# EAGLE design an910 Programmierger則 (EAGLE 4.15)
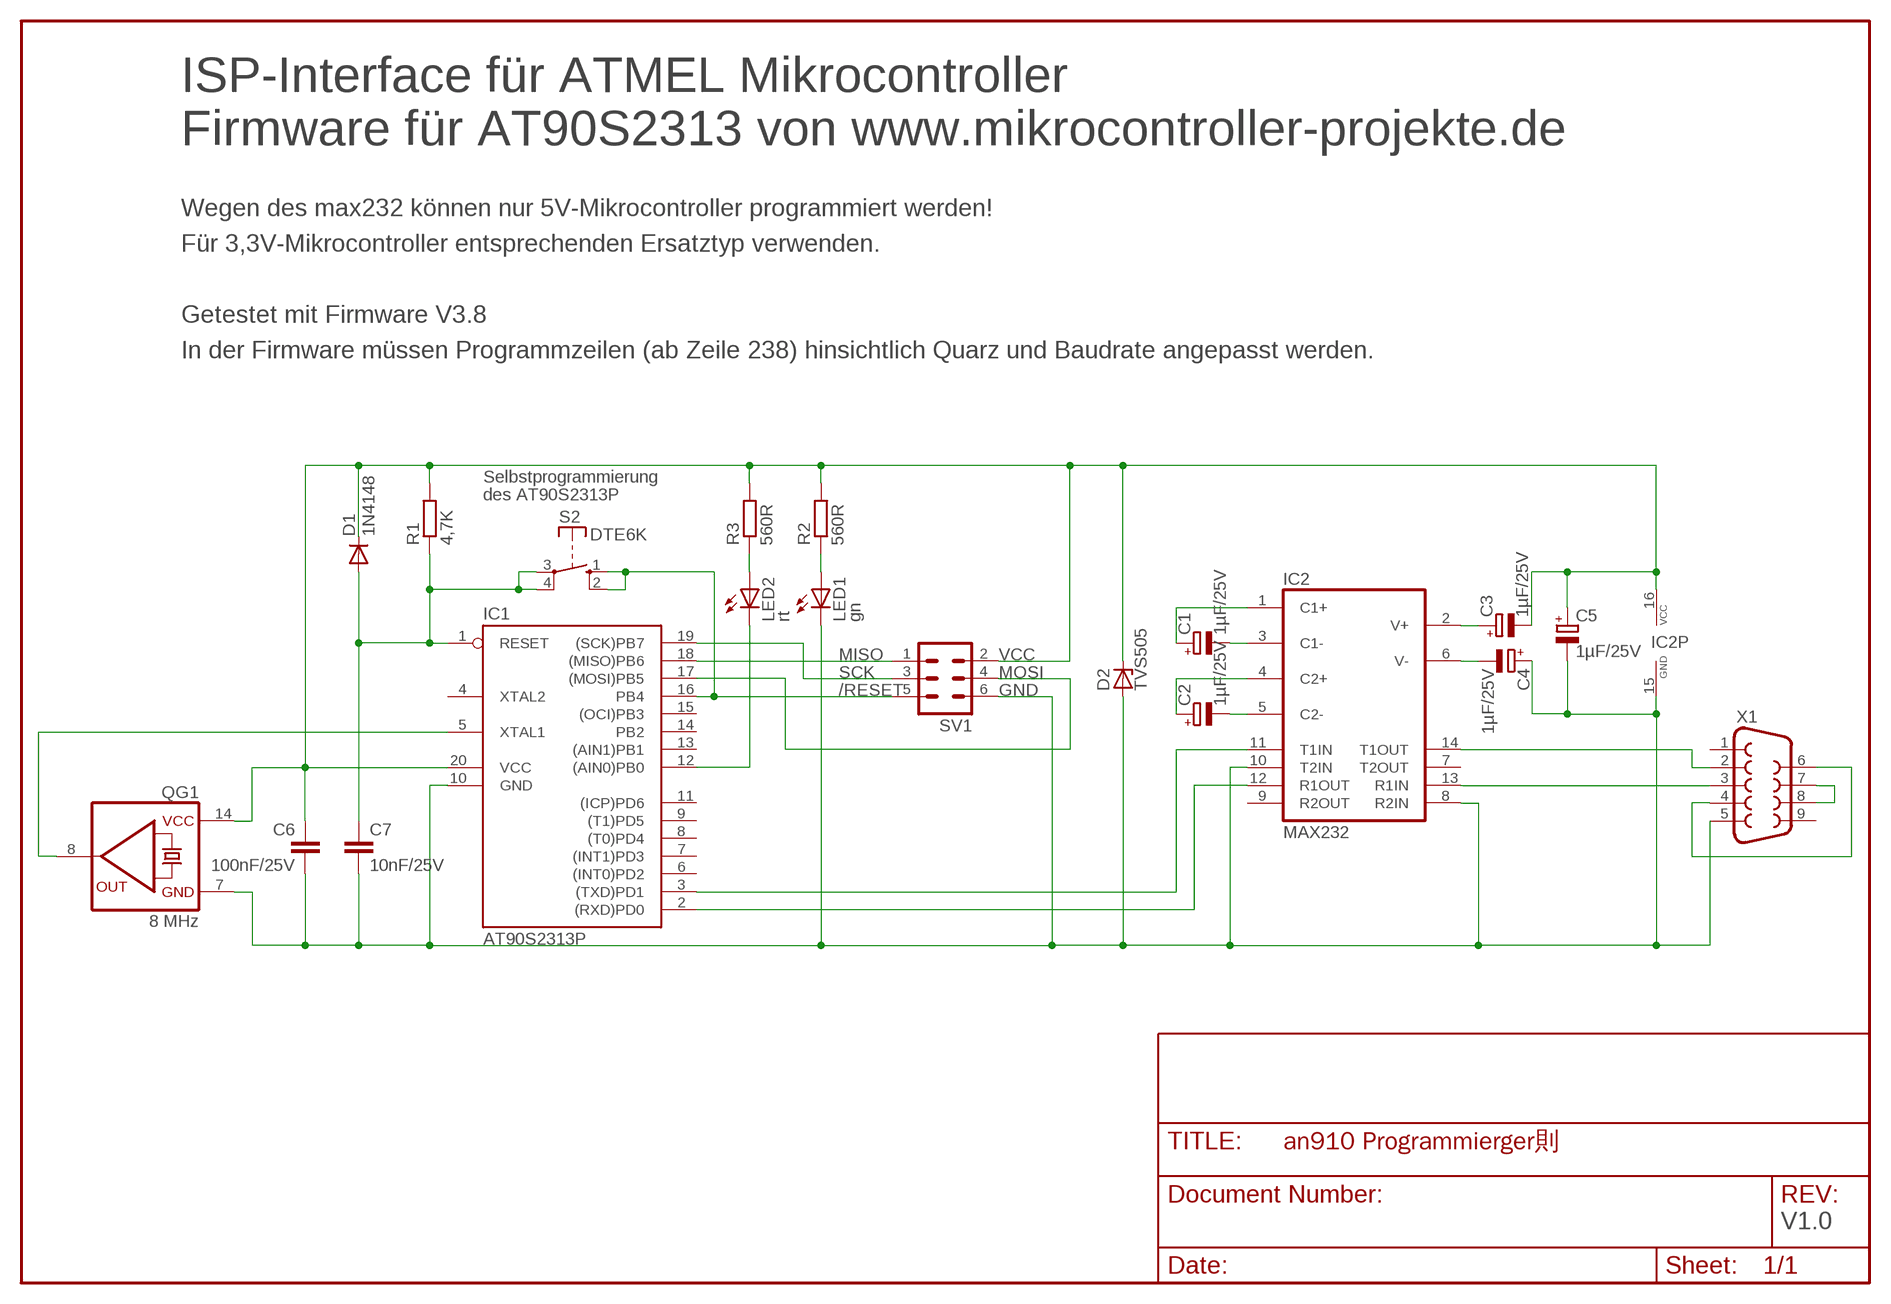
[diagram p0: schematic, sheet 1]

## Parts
C1  1µF/25V  CPOL-EUETR1  [ETR1]
C2  1µF/25V  CPOL-EUETR1  [ETR1]
C3  1µF/25V  CPOL-EUETR1  [ETR1]
C4  1µF/25V  CPOL-EUETR1  [ETR1]
C5  1µF/25V  CPOL-EUETR1  [ETR1]
C6  100nF/25V  C-EU050-030X075  [C050-030X075]
C7  10nF/25V  C-EU050-030X075  [C050-030X075]
D1  1N4148  [DO35-10]
D2  TVS505  ZY  [P1Z12]
IC1  AT90S2313P  [DIL20]
IC2  MAX232  [DIL16]
LED1  gn  LED3MM  [LED3MM]
LED2  rt  LED3MM  [LED3MM]
QG1  8 MHz  QG5860  [DIL14S]
R1  4,7K  R-EU_0207/10  [0207/10]
R2  560R  R-EU_0207/10  [0207/10]
R3  560R  R-EU_0207/10  [0207/10]
S2  DTE6K  [DTE6K]
SV1  MA03-2  [MA03-2]
X1  F09H  [F09H]

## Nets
N$1: C2.- IC2.5(C2-)
N$2: C2.+ IC2.4(C2+)
N$3: C1.- IC2.3(C1-)
N$4: C1.+ IC2.1(C1+)
N$5: IC1.12((AIN0)PB0) LED2.K(C)
N$6: IC1.3((TXD)PD1) IC2.11(T1IN)
N$7: C4.- IC2.6(V-)
N$8: C3.+ IC2.2(V+)
N$9: IC1.18((MISO)PB6) SV1.1
N$10: C3.- C5.+ C6.1 D1.C D2.C IC1.20(VCC) IC2.16(VCC) QG1.14(VCC) R1.2 R2.2 R3.2 SV1.2
N$12: IC1.2((RXD)PD0) IC2.12(R1OUT)
N$13: IC2.14(T1OUT) X1.2
N$14: IC2.13(R1IN) X1.3
N$15: X1.7 X1.8
N$16: X1.4 X1.6
N$17: IC1.19((SCK)PB7) SV1.3
N$18: IC1.5(XTAL1) QG1.8(OUT)
N$19: IC1.17((MOSI)PB5) SV1.4
N$20: IC1.16(PB4) S2.1(S) S2.2(S) SV1.5
N$21: LED1.A R2.1
N$22: C7.1 D1.A IC1.1(RESET) R1.1 S2.3(P) S2.4(P)
N$23: LED2.A R3.1
N$24: C4.+ C5.- C6.2 C7.2 D2.A IC1.10(GND) IC2.8(R2IN) IC2.10(T2IN) IC2.15(GND) LED1.K(C) QG1.7(GND) SV1.6 X1.5
Unconnected: IC1.4(XTAL2) IC1.6((INT0)PD2) IC1.7((INT1)PD3) IC1.8((T0)PD4) IC1.9((T1)PD5) IC1.11((ICP)PD6) IC1.13((AIN1)PB1) IC1.14(PB2) IC1.15((OCI)PB3) IC2.7(T2OUT) IC2.9(R2OUT) X1.1 X1.9

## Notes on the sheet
- ISP-Interface für ATMEL Mikrocontroller
- Firmware für AT90S2313 von www.mikrocontroller-projekte.de
- Wegen des max232 können nur 5V-Mikrocontroller programmiert werden!
- Für 3,3V-Mikrocontroller entsprechenden Ersatztyp verwenden.
- Getestet mit Firmware V3.8
- In der Firmware müssen Programmzeilen (ab Zeile 238) hinsichtlich Quarz und Baudrate angepasst werden.
- Selbstprogrammierung
- des AT90S2313P
- MISO | VCC
- SCK | MOSI
- /RESET | GND
- V1.0

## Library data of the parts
C1-C5 = rcl:CPOL-EU: POLARIZED CAPACITOR, European symbol
C6 C7 = rcl:C-EU: CAPACITOR, European symbol
D1 = diode:1N4148: DIODE
D2 = diode:ZY: Z DIODE
IC1 = atmel:AT90S2313: MICROCONTROLLER 2 Kbytes FLASH 128 bytes SRAM 128 bytes EEPROM UART
IC2 = maxim:MAX232: RS232 TRANSEIVER
LED1 LED2 = led:LED: LED
QG1 = crystal:QG5860: CRYSTAL RESONATOR
R1-R3 = rcl:R-EU_: RESISTOR, European symbol
S2 = switch-misc:DT: ITT SWITCH
SV1 = con-lstb:MA03-2: PIN HEADER
X1 = con-subd:F09: SUB-D

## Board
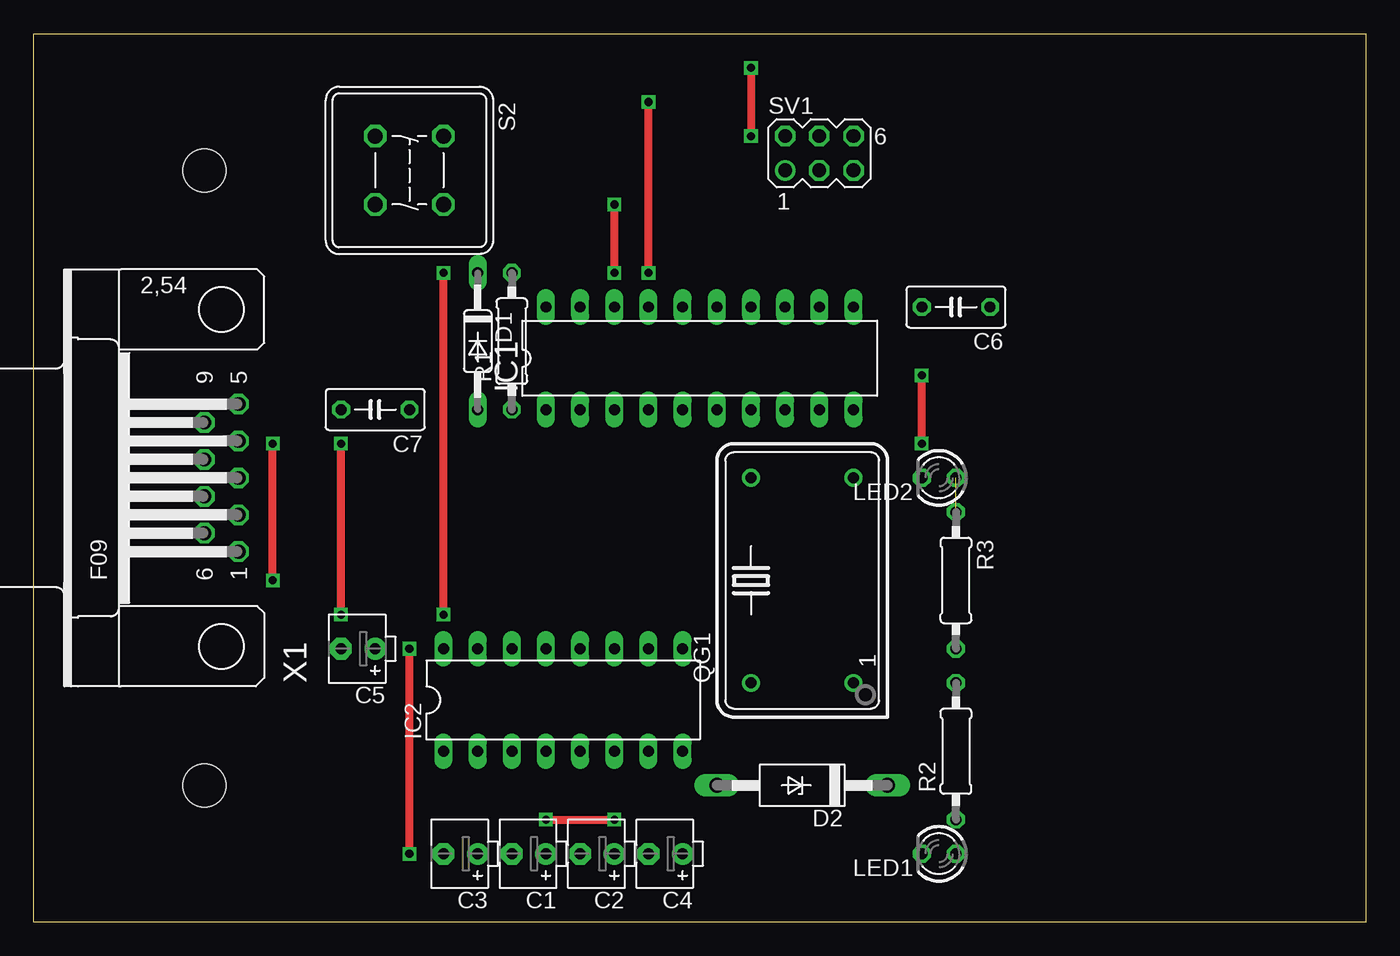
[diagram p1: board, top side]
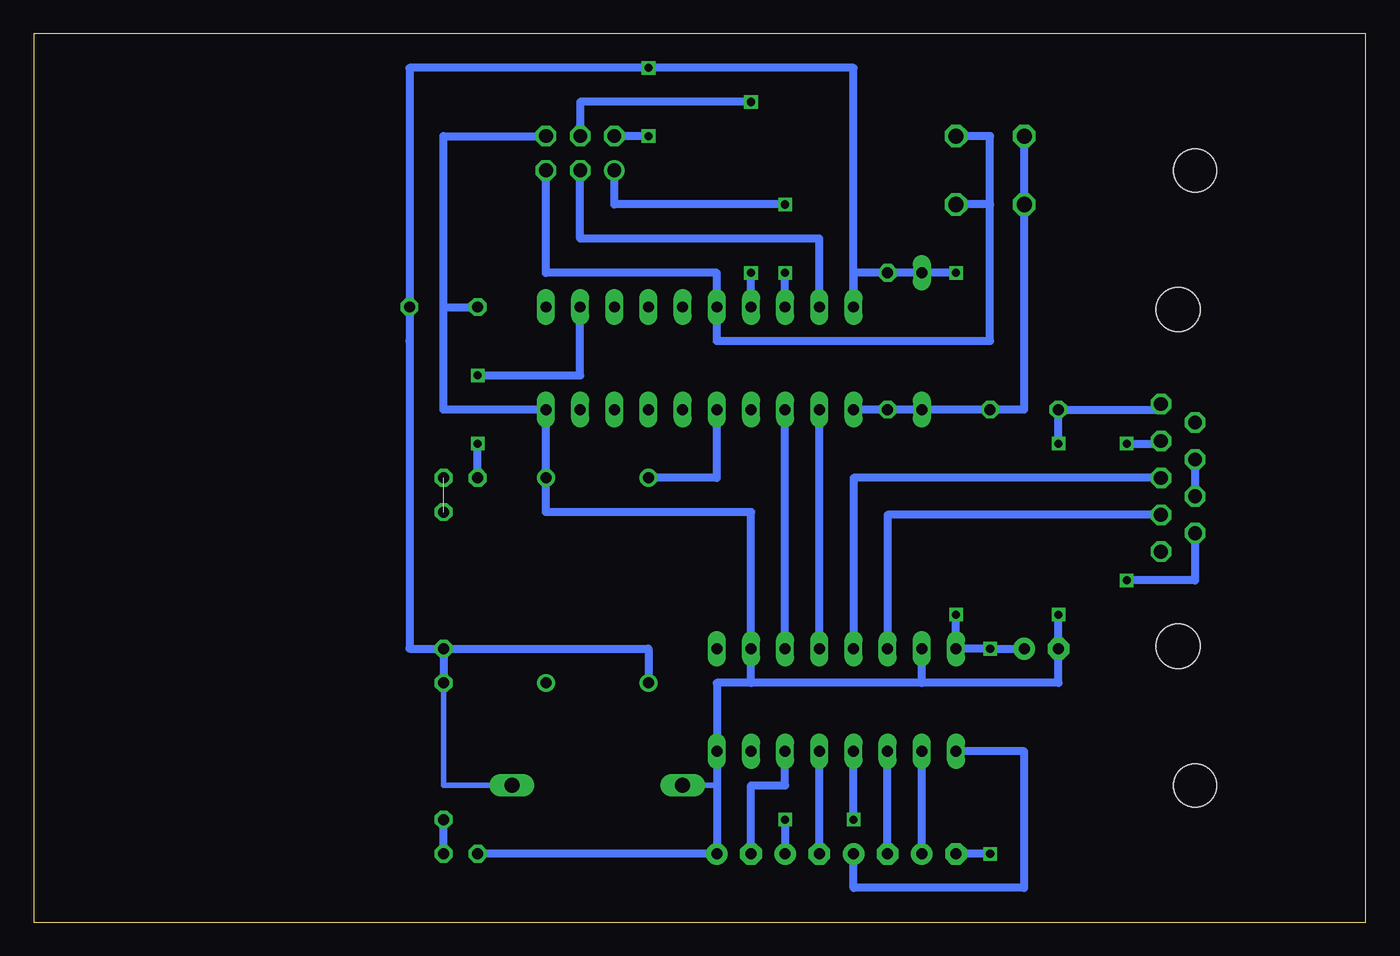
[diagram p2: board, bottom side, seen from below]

Size 99.06 x 66.04 mm. Coordinates in mm from the lower left corner, seen from the top.
Outline: 0,0 0,66.04 99.06,66.04 99.06,0 0,0
Copper layers (1*16): Top 0.035mm / dielectric 1.5mm / Bottom 0.035mm
Design rules "default": minimum track width 10mil, minimum drill 24mil, track to track 8mil, track to pad 8mil, pad to pad 8mil, via to via 8mil, smd to smd 8mil, copper to edge 40mil, drill to drill 8mil, minimum pad ring 10mil, minimum via ring 8mil, stop-mask expansion 4mil, vias tented up to drill 0mil, thermal gap 10mil
Holes 3.2 mm at 12.7,55.88 12.7,10.16

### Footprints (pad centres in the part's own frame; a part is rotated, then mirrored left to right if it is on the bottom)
ETR1 = drill 0.813 pad 1.6 round: + -1.27,0 | drill 0.813 pad 1.6 octagon: - 1.27,0
C050-030X075 = drill 0.813 octagon: 1 -2.54,0; 2 2.54,0
DO35-10 = drill 0.813 long: A 5.08,0; C -5.08,0
P1Z12 = drill 1.118 long: A 6.35,0; C -6.35,0
DIL20 = drill 0.813 long: 1 -11.43,-3.81; 2 -8.89,-3.81; 3 -6.35,-3.81; 4 -3.81,-3.81; 5 -1.27,-3.81; 6 1.27,-3.81; 7 3.81,-3.81; 8 6.35,-3.81; 9 8.89,-3.81; 10 11.43,-3.81; 11 11.43,3.81; 12 8.89,3.81; 13 6.35,3.81; 14 3.81,3.81; 15 1.27,3.81; 16 -1.27,3.81; 17 -3.81,3.81; 18 -6.35,3.81; 19 -8.89,3.81; 20 -11.43,3.81
DIL16 = drill 0.813 long: 1 -8.89,-3.81; 2 -6.35,-3.81; 3 -3.81,-3.81; 4 -1.27,-3.81; 5 1.27,-3.81; 6 3.81,-3.81; 7 6.35,-3.81; 8 8.89,-3.81; 9 8.89,3.81; 10 6.35,3.81; 11 3.81,3.81; 12 1.27,3.81; 13 -1.27,3.81; 14 -3.81,3.81; 15 -6.35,3.81; 16 -8.89,3.81
LED3MM = drill 0.813 octagon: A -1.27,0; K 1.27,0
DIL14S = drill 0.813 round: 1 -7.62,-3.81; 7 7.62,-3.81; 8 7.62,3.81; 14 -7.62,3.81
0207/10 = drill 0.813 octagon: 1 -5.08,0; 2 5.08,0
DTE6K = drill 1.118 octagon: 1 -2.54,2.54; 2 2.54,2.54; 3 2.54,-2.54; 4 -2.54,-2.54
MA03-2 = drill 1.016 round: 1 -2.54,-1.27 | drill 1.016 octagon: 2 -2.54,1.27; 3 0,-1.27; 4 0,1.27; 5 2.54,-1.27; 6 2.54,1.27
F09H = drill 1.016 octagon: 1 -5.486,-1.27; 2 -2.743,-1.27; 3 0,-1.27; 4 2.743,-1.27; 5 5.486,-1.27; 6 -4.115,1.27; 7 -1.372,1.27; 8 1.372,1.27; 9 4.115,1.27 | hole 3.302: -12.522,0; 12.522,0

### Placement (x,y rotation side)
C1  36.83,5.08 180 top
C2  41.91,5.08 180 top
C3  31.75,5.08 180 top
C4  46.99,5.08 180 top
C5  24.13,20.32 180 top
C6  68.58,45.72 180 top
C7  25.4,38.1 180 top
D1  33.02,43.18 270 top
D2  57.15,10.16 180 top
IC1  49.53,41.91 0 top
IC2  39.37,16.51 0 top
LED1  67.31,5.08 180 top
LED2  67.31,33.02 180 top
QG1  57.15,25.4 90 top
R1  35.56,43.18 90 top
R2  68.58,12.7 90 top
R3  68.58,25.4 270 top
S2  27.94,55.88 270 top
SV1  58.42,57.15 0 top
X1  13.97,33.02 90 top

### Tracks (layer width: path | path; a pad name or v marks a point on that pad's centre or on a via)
N$1
  Bottom 0.61: C2.- IC2.5
N$2  (via drill 0.6)
  Top 0.61: v38.1,7.62 v43.18,7.62
  Bottom 0.61: v43.18,7.62 C2.+ | v38.1,7.62 IC2.4
N$3
  Bottom 0.61: C1.- IC2.3
N$4
  Bottom 0.61: C1.+ 38.1,2.54 25.4,2.54 25.4,12.7 IC2.1
N$5  (via drill 0.6)
  Top 0.61: v66.04,35.56 v66.04,40.64
  Bottom 0.61: IC1.12 58.42,40.64 v66.04,40.64 | LED2.K v66.04,35.56
N$6
  Bottom 0.61: IC2.11 IC1.3
N$7
  Bottom 0.61: C4.- 45.72,10.16 43.18,10.16 IC2.6
N$8
  Bottom 0.61: C3.+ IC2.2
N$9  (via drill 0.6)
  Top 0.61: v43.18,48.26 v43.18,53.34
  Bottom 0.61: v43.18,53.34 55.88,53.34 SV1.1 | IC1.18 v43.18,48.26
N$10  (via drill 0.6)
  Top 0.61: v27.94,5.08 v27.94,20.32 | v30.48,22.86 v30.48,48.26 | v53.34,63.5 v53.34,58.42
  Bottom 0.406: D2.C 68.58,10.16 R2.2
  Bottom 0.61: v27.94,5.08 C3.- | v27.94,20.32 IC2.16 | v27.94,20.32 C5.+ | v27.94,20.32 IC2.16 | IC2.16 v30.48,22.86 | v30.48,48.26 D1.C R1.2 38.1,48.26 IC1.20 38.1,63.5 v53.34,63.5 71.12,63.5 C6.1 | QG1.14 53.34,20.32 R3.2 | R3.2 71.12,20.32 C6.1 | C6.1 71.12,43.18 | v53.34,58.42 SV1.2 | R3.2 R2.2
N$12
  Bottom 0.61: IC2.12 IC1.2
N$13
  Bottom 0.61: X1.2 35.56,30.28 IC2.14
N$14
  Bottom 0.61: X1.3 38.1,33.02 IC2.13
N$15
  Bottom 0.61: X1.7 X1.8
N$16  (via drill 0.6)
  Top 0.61: v17.78,25.4 v17.78,35.56
  Bottom 0.61: X1.6 12.7,25.4 v17.78,25.4 | X1.4 15.24,35.56 v17.78,35.56
N$17
  Bottom 0.61: IC1.19 40.64,50.8 58.42,50.8 SV1.3
N$18
  Bottom 0.61: QG1.8 48.26,33.02 IC1.5
N$19  (via drill 0.6)
  Top 0.61: v45.72,48.26 v45.72,60.96
  Bottom 0.61: SV1.4 58.42,60.96 v45.72,60.96 | IC1.17 v45.72,48.26
N$20
  Bottom 0.61: 27.94,53.34 27.94,43.18 48.26,43.18 IC1.16 48.26,48.26 60.96,48.26 SV1.5 | 27.94,53.34 S2.2 | 27.94,53.34 27.94,58.42 S2.1
N$21
  Bottom 0.61: LED1.A R2.1
N$22
  Bottom 0.61: S2.4 S2.3 25.4,38.1 C7.1 D1.A R1.1 IC1.1
N$23  (1 unrouted)
N$24  (via drill 0.6)
  Top 0.61: v22.86,22.86 v22.86,35.56
  Bottom 0.406: 48.26,10.16 D2.A
  Bottom 0.61: 45.72,17.78 48.26,17.78 IC2.8 48.26,10.16 C4.+ LED1.K | 45.72,17.78 IC2.10 45.72,30.48 60.96,30.48 QG1.7 IC1.10 68.58,38.1 68.58,45.72 | 33.02,17.78 45.72,17.78 | 33.02,17.78 IC2.15 | 33.02,17.78 22.86,17.78 C5.- v22.86,22.86 | X1.5 15.24,38.1 C7.2 v22.86,35.56 | 68.58,45.72 C6.2 | 68.58,45.72 68.58,58.42 SV1.6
